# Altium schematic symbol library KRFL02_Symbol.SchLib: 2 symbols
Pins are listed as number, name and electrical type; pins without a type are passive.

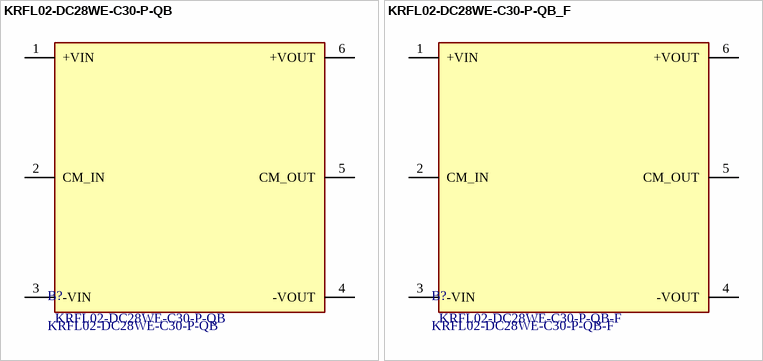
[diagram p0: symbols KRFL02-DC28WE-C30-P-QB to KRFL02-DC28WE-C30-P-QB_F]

## KRFL02-DC28WE-C30-P-QB
designator B?
30A Passive EMI Filter Quarter Brick; MFG: KOLT
pins: 1 +VIN, 2 CM_IN, 3 -VIN, 4 -VOUT, 5 CM_OUT, 6 +VOUT

## KRFL02-DC28WE-C30-P-QB_F
designator B?, comment KRFL02-DC28WE-C30-P-QB-F
30A Passive EMI Filter Quarter Brick; MFG: KOLT
pins: 1 +VIN, 2 CM_IN, 3 -VIN, 4 -VOUT, 5 CM_OUT, 6 +VOUT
